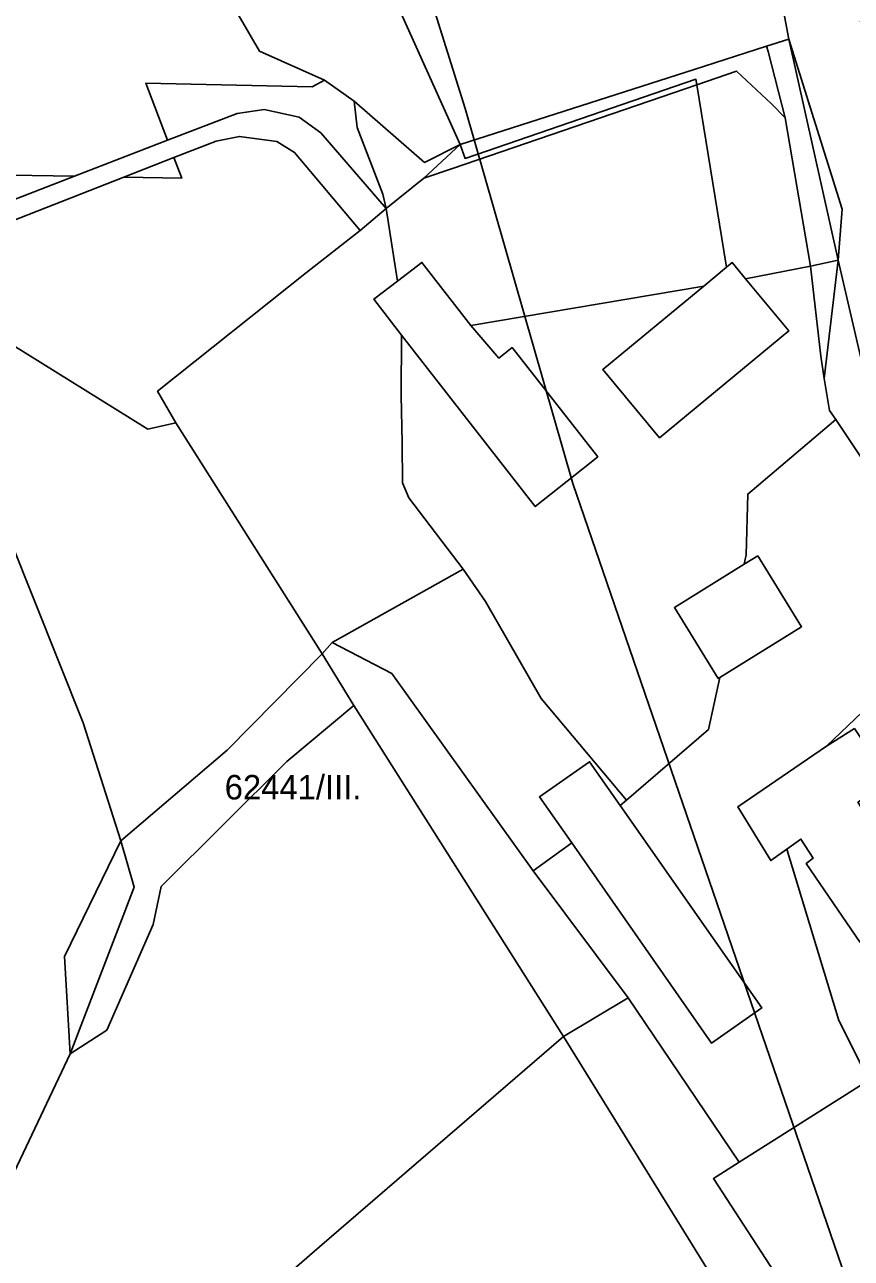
# Model space of a CAD drawing. Extents: x -521261 to -517465, y -1182764 to -1179456.
# Drawn here: x -519517.8 to -519349.2, y -1181804 to -1181552.4 of the extents above; entities that cross this region are included whole.
import ezdxf

# ---------------------------------------------------------------- set-up
doc = ezdxf.new("R2010")
doc.units = 0
for name, color, linetype in [('95610013', 7, 'Continuous'), ('95630013', 7, 'Continuous'), ('95640013', 7, 'Continuous'), ('95660013', 7, 'Continuous')]:
    doc.layers.add(name, color=color, linetype=linetype)

msp = doc.modelspace()

# ---------------------------------------------------------------- linework, layer by layer
at = {"layer": '95610013'}
for points in [[(-519478.73, -1181464.87), (-519470.94, -1181484.78), (-519456.38, -1181500.18), (-519448.41, -1181519.82), (-519446.59, -1181537.72), (-519428.99, -1181576.87), (-519436.26, -1181580.5), (-519450.63, -1181567.98), (-519456.65, -1181563.71), (-519469.92, -1181557.79), (-519509.72, -1181489.33), (-519511.19, -1181486.58)], [(-519509.72, -1181489.33), (-519469.92, -1181557.79), (-519456.65, -1181563.71), (-519459.18, -1181565.12), (-519493.06, -1181564.31), (-519488.66, -1181575.99), (-519507.62, -1181583.34), (-519525.03, -1181583.04), (-519550.78, -1181568.23), (-519553.52, -1181572.42), (-519543.61, -1181581.76), (-519547.14, -1181593.89), (-519562.84, -1181596.65), (-519576.31, -1181603.51), (-519563.51, -1181548.93), (-519560.91, -1181533.55), (-519560.59, -1181527.09), (-519562.54, -1181512.84), (-519534.8, -1181505.37)], [(-519459.18, -1181565.12), (-519456.65, -1181563.71), (-519450.63, -1181567.98), (-519450.01, -1181573.37), (-519444.75, -1181586.95), (-519444.05, -1181589.92), (-519457.38, -1181574.5), (-519461.85, -1181571.29), (-519468.92, -1181569.73), (-519474.47, -1181570.5), (-519488.66, -1181575.99), (-519493.06, -1181564.31)], [(-519553.52, -1181572.42), (-519550.78, -1181568.23), (-519525.03, -1181583.04), (-519507.62, -1181583.34), (-519546.36, -1181598.36), (-519547.14, -1181593.89), (-519543.61, -1181581.76)], [(-519478.73, -1181576.14), (-519474.01, -1181575.19), (-519466.37, -1181576.22), (-519462.75, -1181578.47), (-519449.37, -1181594.38), (-519460.32, -1181602.95), (-519490.67, -1181627.18), (-519486.95, -1181633.64), (-519492.65, -1181634.89), (-519545.26, -1181602.19), (-519497.59, -1181583.52), (-519485.75, -1181583.73), (-519487.34, -1181579.51)], [(-519497.59, -1181583.52), (-519487.34, -1181579.51), (-519485.75, -1181583.73)], [(-519565.03, -1181610.38), (-519545.26, -1181602.19), (-519520.75, -1181657.44), (-519505.86, -1181694.79), (-519498.2, -1181718.82), (-519509.68, -1181742.43), (-519508.54, -1181762.3), (-519521.69, -1181790.12), (-519524.04, -1181797.09), (-519527.59, -1181810.9), (-519531.67, -1181805.67), (-519538.74, -1181776.21), (-519558.85, -1181712.23), (-519574.34, -1181678.1), (-519578.35, -1181654.41), (-519578.54, -1181638.45), (-519578.07, -1181621.73)], [(-519492.65, -1181634.89), (-519486.95, -1181633.64), (-519457.1, -1181680.7), (-519476.47, -1181700.33), (-519498.2, -1181718.82), (-519505.86, -1181694.79), (-519520.75, -1181657.44), (-519545.26, -1181602.19)], [(-519464.34, -1181702.69), (-519450.65, -1181691.27), (-519407.91, -1181758.76), (-519457.7, -1181801.62), (-519514.79, -1181851.2), (-519527.59, -1181810.9), (-519524.04, -1181797.09), (-519521.69, -1181790.12), (-519508.54, -1181762.3), (-519501.06, -1181757.42), (-519491.57, -1181735.94), (-519489.97, -1181728.17)], [(-519407.91, -1181758.76), (-519323.87, -1181894.73), (-519320.13, -1181908.75), (-519359.11, -1181915.9), (-519379.46, -1181920.51), (-519406.37, -1181926.58), (-519413.61, -1181928.2), (-519432.89, -1181931.4), (-519465.56, -1181934.8), (-519514.79, -1181851.2), (-519457.7, -1181801.62)]]:
    msp.add_lwpolyline(points, close=True, dxfattribs=at)
at = {"layer": '95630013'}
msp.add_lwpolyline([(-519347.34, -1181551.68), (-519338.86, -1181596.87), (-519345.68, -1181614.13), (-519345.73, -1181624.05), (-519341.9, -1181626.93), (-519332.99, -1181636), (-519329.7, -1181643.01), (-519326.48, -1181650.26), (-519315.31, -1181658.6), (-519310.43, -1181664.25), (-519295.01, -1181696.26), (-519298.01, -1181706.05), (-519305.33, -1181696.42), (-519321.38, -1181668.9), (-519344.46, -1181632.66), (-519351.95, -1181600.47), (-519351.13, -1181590.07), (-519362.01, -1181555.36), (-519364.56, -1181541.56)], dxfattribs=at)
msp.add_lwpolyline([(-519362.01, -1181555.36), (-519351.13, -1181590.07), (-519351.95, -1181600.47)], close=True, dxfattribs=at)
at = {"layer": '95640013'}
for points in [[(-519415.62, -1181448.49), (-519397.54, -1181441.8), (-519386.52, -1181476.56), (-519380.95, -1181493.03), (-519364.56, -1181541.56), (-519362.01, -1181555.36), (-519366.5, -1181556.79), (-519381.3, -1181561.55), (-519428.99, -1181576.87), (-519446.59, -1181537.72), (-519448.41, -1181519.82), (-519456.38, -1181500.18), (-519470.94, -1181484.78), (-519478.73, -1181464.87), (-519461.71, -1181462.1), (-519460.63, -1181463.59), (-519429.99, -1181453.33)], [(-519366.5, -1181556.79), (-519362.01, -1181555.36), (-519351.95, -1181600.47), (-519357.53, -1181601.68), (-519362.74, -1181571.4), (-519366.21, -1181557.91)], [(-519366.21, -1181557.91), (-519362.74, -1181571.4), (-519365.53, -1181568.53), (-519372.66, -1181561.89), (-519380.75, -1181564.7), (-519380.92, -1181563.53), (-519427.98, -1181579.69), (-519428.99, -1181576.87), (-519381.3, -1181561.55), (-519366.5, -1181556.79)], [(-519380.75, -1181564.7), (-519372.66, -1181561.89), (-519365.53, -1181568.53), (-519362.74, -1181571.4), (-519357.53, -1181601.68), (-519370.78, -1181604.23), (-519373.51, -1181600.92), (-519374.67, -1181601.88)], [(-519380.75, -1181564.7), (-519374.67, -1181601.88), (-519379.34, -1181605.75), (-519426.79, -1181613.78), (-519436.79, -1181600.91), (-519441.76, -1181604.71), (-519444.05, -1181589.92), (-519436.43, -1181583.74), (-519430.52, -1181581.72), (-519385.48, -1181566.31)], [(-519380.75, -1181564.7), (-519385.48, -1181566.31), (-519430.52, -1181581.72), (-519436.43, -1181583.74), (-519428.99, -1181576.87), (-519427.98, -1181579.69), (-519380.92, -1181563.53)], [(-519450.63, -1181567.98), (-519436.26, -1181580.5), (-519428.99, -1181576.87), (-519436.43, -1181583.74), (-519444.05, -1181589.92), (-519444.75, -1181586.95), (-519450.01, -1181573.37)], [(-519468.92, -1181569.73), (-519461.85, -1181571.29), (-519457.38, -1181574.5), (-519444.05, -1181589.92), (-519449.37, -1181594.38), (-519462.75, -1181578.47), (-519466.37, -1181576.22), (-519474.01, -1181575.19), (-519478.73, -1181576.14), (-519487.34, -1181579.51), (-519497.59, -1181583.52), (-519545.26, -1181602.19), (-519546.36, -1181598.36), (-519507.62, -1181583.34), (-519488.66, -1181575.99), (-519474.47, -1181570.5)], [(-519449.37, -1181594.38), (-519444.05, -1181589.92), (-519441.76, -1181604.71), (-519446.59, -1181608.38), (-519440.98, -1181615.74), (-519441.04, -1181628.05), (-519440.81, -1181637.71), (-519440.77, -1181645.87), (-519439.49, -1181648.89), (-519428.35, -1181663.44), (-519455.08, -1181678.42), (-519457.1, -1181680.7), (-519486.95, -1181633.64), (-519490.67, -1181627.18), (-519460.32, -1181602.95)], [(-519357.53, -1181601.68), (-519351.95, -1181600.47), (-519354.8, -1181624.6), (-519355.42, -1181620.01)], [(-519354.8, -1181624.6), (-519351.95, -1181600.47), (-519344.46, -1181632.66), (-519321.38, -1181668.9), (-519336.06, -1181657.41), (-519352.42, -1181632.95), (-519353.71, -1181631.09)], [(-519436.79, -1181600.91), (-519426.79, -1181613.78), (-519421.09, -1181620.42), (-519418.39, -1181618.26), (-519400.95, -1181640.52), (-519403.93, -1181642.92), (-519413.68, -1181650.7), (-519440.98, -1181615.74), (-519446.59, -1181608.38), (-519441.76, -1181604.71)], [(-519370.78, -1181604.23), (-519357.53, -1181601.68), (-519355.42, -1181620.01), (-519354.8, -1181624.6), (-519353.71, -1181631.09), (-519352.42, -1181632.95), (-519370.37, -1181648.12), (-519370.66, -1181660.52), (-519371.08, -1181662.44), (-519385.31, -1181671.29), (-519376.36, -1181685.73), (-519376.06, -1181685.55), (-519378.34, -1181696.12), (-519395.09, -1181710.54), (-519412.46, -1181689.81), (-519423.84, -1181670.06), (-519428.35, -1181663.44), (-519439.49, -1181648.89), (-519440.77, -1181645.87), (-519440.81, -1181637.71), (-519441.04, -1181628.05), (-519440.98, -1181615.74), (-519413.68, -1181650.7), (-519403.93, -1181642.92), (-519400.95, -1181640.52), (-519418.39, -1181618.26), (-519421.09, -1181620.42), (-519426.79, -1181613.78), (-519379.34, -1181605.75), (-519399.88, -1181622.71), (-519388.33, -1181636.64), (-519362, -1181614.88)], [(-519373.51, -1181600.92), (-519370.78, -1181604.23), (-519362, -1181614.88), (-519388.33, -1181636.64), (-519399.88, -1181622.71), (-519379.34, -1181605.75), (-519374.67, -1181601.88)], [(-519352.42, -1181632.95), (-519336.06, -1181657.41), (-519326.47, -1181673.05), (-519354.29, -1181699.53), (-519372.38, -1181711.93), (-519365.67, -1181722.88), (-519362.38, -1181720.52), (-519351.79, -1181755.5), (-519345.68, -1181767.66), (-519372.1, -1181784.4), (-519394.71, -1181750.87), (-519414.1, -1181724.96), (-519406.22, -1181719.23), (-519377.75, -1181760.09), (-519367.51, -1181752.91), (-519396.35, -1181711.66), (-519395.09, -1181710.54), (-519378.34, -1181696.12), (-519376.06, -1181685.55), (-519359.36, -1181675.18), (-519368.32, -1181660.74), (-519371.08, -1181662.44), (-519370.66, -1181660.52), (-519370.37, -1181648.12)], [(-519371.08, -1181662.44), (-519368.32, -1181660.74), (-519359.36, -1181675.18), (-519376.06, -1181685.55), (-519376.36, -1181685.73), (-519385.31, -1181671.29)], [(-519428.35, -1181663.44), (-519423.84, -1181670.06), (-519412.46, -1181689.81), (-519395.09, -1181710.54), (-519396.35, -1181711.66), (-519402.6, -1181702.71), (-519412.84, -1181709.88), (-519406.22, -1181719.23), (-519414.1, -1181724.96), (-519442.93, -1181684.69), (-519455.08, -1181678.42)], [(-519455.08, -1181678.42), (-519442.93, -1181684.69), (-519414.1, -1181724.96), (-519394.71, -1181750.87), (-519407.91, -1181758.76), (-519450.65, -1181691.27), (-519457.1, -1181680.7)], [(-519450.65, -1181691.27), (-519464.34, -1181702.69), (-519489.97, -1181728.17), (-519491.57, -1181735.94), (-519501.06, -1181757.42), (-519508.54, -1181762.3), (-519495.45, -1181728.28), (-519498.2, -1181718.82), (-519476.47, -1181700.33), (-519457.1, -1181680.7)], [(-519354.29, -1181699.53), (-519348.62, -1181695.96), (-519341.38, -1181706.76), (-519347.9, -1181710.98), (-519345.53, -1181714.62), (-519344.13, -1181713.73), (-519333.71, -1181730.21), (-519340.2, -1181734.59), (-519338.12, -1181737.78), (-519343.27, -1181741.3), (-519345.37, -1181738.12), (-519347.41, -1181739.55), (-519358.42, -1181723.46), (-519357.03, -1181722.39), (-519359.51, -1181718.49), (-519362.38, -1181720.52), (-519365.67, -1181722.88), (-519372.38, -1181711.93)], [(-519412.84, -1181709.88), (-519402.6, -1181702.71), (-519396.35, -1181711.66), (-519367.51, -1181752.91), (-519377.75, -1181760.09), (-519406.22, -1181719.23)], [(-519498.2, -1181718.82), (-519495.45, -1181728.28), (-519508.54, -1181762.3), (-519509.68, -1181742.43)], [(-519394.71, -1181750.87), (-519372.1, -1181784.4), (-519377.35, -1181787.73), (-519340.07, -1181844.99), (-519338.54, -1181844.01), (-519337.53, -1181845.79), (-519332.33, -1181864.19), (-519332, -1181866.16), (-519333.66, -1181867.18), (-519330.23, -1181872.71), (-519323.87, -1181894.73), (-519407.91, -1181758.76)], [(-519345.68, -1181767.66), (-519308.37, -1181824.89), (-519319.58, -1181831.93), (-519322.19, -1181833.6), (-519338.54, -1181844.01), (-519340.07, -1181844.99), (-519377.35, -1181787.73), (-519372.1, -1181784.4)]]:
    msp.add_lwpolyline(points, close=True, dxfattribs=at)
for points in [[(-519348.62, -1181695.96), (-519354.29, -1181699.53), (-519326.47, -1181673.05)], [(-519345.68, -1181767.66), (-519351.79, -1181755.5), (-519362.38, -1181720.52), (-519359.51, -1181718.49), (-519357.03, -1181722.39), (-519358.42, -1181723.46), (-519347.41, -1181739.55)]]:
    msp.add_lwpolyline(points, dxfattribs=at)
at = {"layer": '95660013'}
for points in [[(-519443.5, -1181520), (-519428, -1181569.5), (-519406, -1181646), (-519336.5, -1181848.5), (-519328, -1181907), (-519323, -1181997), (-519327, -1182051), (-519350, -1182136.5)], [(-519350, -1182136.5), (-519327, -1182051), (-519323, -1181997), (-519328, -1181907), (-519336.5, -1181848.5), (-519406, -1181646), (-519428, -1181569.5), (-519443.5, -1181520)]]:
    msp.add_lwpolyline(points, dxfattribs=at)

# ---------------------------------------------------------------- texts
msp.add_text('62441/III.', height=5, rotation=0, dxfattribs=at).set_placement((-519477, -1181710.41))

doc.saveas('drawing.dxf')
